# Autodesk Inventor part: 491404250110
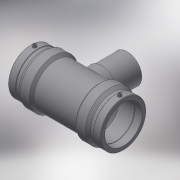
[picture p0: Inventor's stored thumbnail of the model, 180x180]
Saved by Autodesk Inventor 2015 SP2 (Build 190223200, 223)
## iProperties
Created: 2017-06
Part Number: 491404250110
Material: Generic
Description: PLASSON REDUCING TEE 250x110x250
Document SubType Name: Modeling
Designer: KIM
Mass: 15222.6 g
Surface Area: 10500.3 cm^2
Volume: 15222.6 cm^3
Density: 1 g/cm^3
Appearance: Default
Author: KIM
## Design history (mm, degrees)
derived "491404.ipt"
feature "Solid1::491404.ipt"
tag "TaggingFeature1"
body "Solid1"
other parameters: "d0" = 538, "d2" = 326, "d3" = 129, "d4" = 107.6, "d5" = 293.4, "d6" = 237.5, "d8" = 168 deg, "d10" = 51.6, "d11" = 17.2, "d13" = 538, "d14" = 17.6296, "d17" = 225, "d19" = 3.52592, "d20" = 168 deg, "d22" = 303.18, "d23" = 326, "d25" = 135 deg, "d26" = 376.6, "d29" = 152, "d30" = 15, "d31" = 215.2, "d34" = 5 deg, "d35" = 15, "d39" = 5 deg, "d41" = 4, "d42" = 14, "d43" = 0, "d45" = 4, "d46" = 6, "d47" = 0, "d51" = 0, "d52" = 88, "d54" = 0, "d55" = 293.4, "d56" = 326, "d57" = 188.3, "d58" = 135 deg, "d59" = 129, "d60" = 129, "d61" = 135 deg, "d72" = 244.79, "d73" = 122.395, "d75" = 115.5, "d77" = 0, "d78" = 88, "d80" = 0, "d82" = 77, "d83" = 0, "d84" = 3, "d85" = 0, "d86" = 43, "d87" = 297.1164, "d88" = 17.2, "d89" = 3, "d90" = 0, "L_" = 538, "L_1" = 129, "D_" = 326, "A_" = 152, "d_2" = 12
